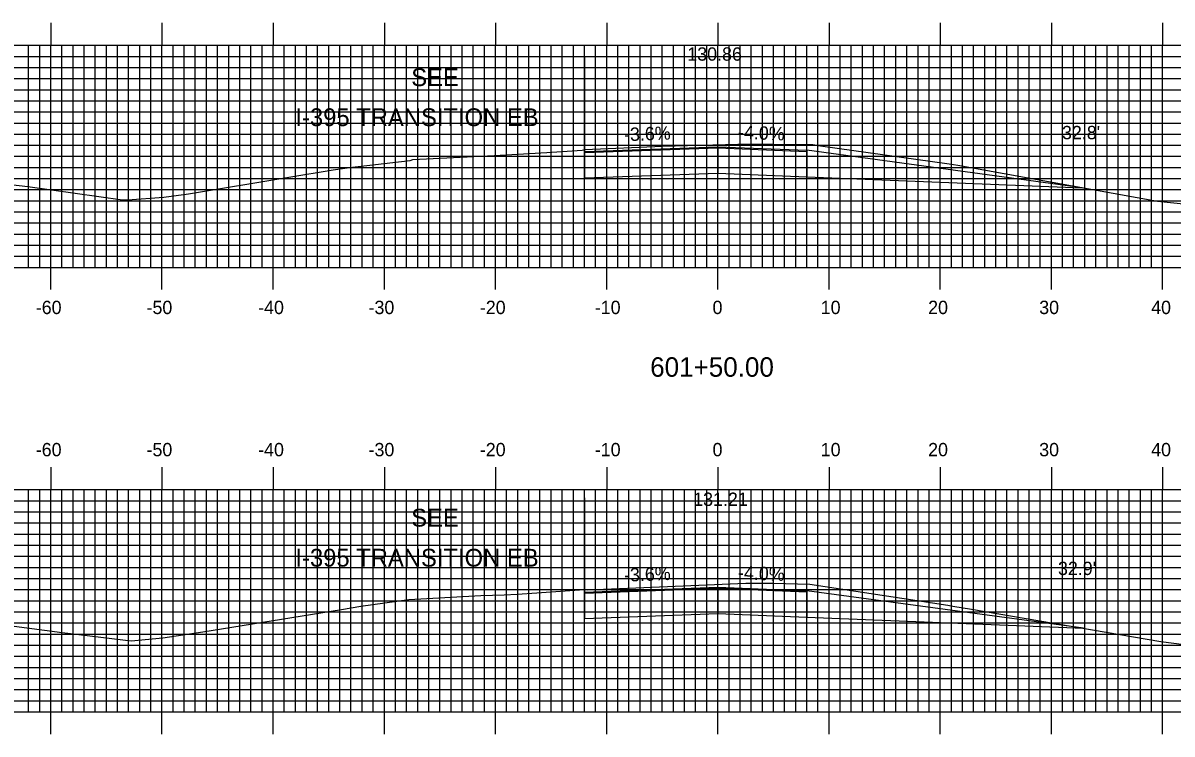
# Model space of a CAD drawing. Extents: x 841388 to 841731, y 363538 to 363758.
# Drawn here: x 841491.4 to 841594.7, y 363633.7 to 363697.7 of the extents above; entities that cross this region are included whole.
import ezdxf

# ---------------------------------------------------------------- set-up
doc = ezdxf.new("R2010")
doc.units = 0
for name, color, linetype in [('ANNOTATION', 7, 'Continuous'), ('D_Roadway_Centerline', 7, 'Continuous'), ('D_Roadway_Centerline_Text', 7, 'Continuous'), ('D_Roadway_Edge_Shoulder', 7, 'Continuous'), ('D_Roadway_Edge_TW', 7, 'Continuous'), ('D_Roadway_SubGrade', 7, 'Continuous'), ('D_Text_Standard', 7, 'Continuous'), ('H_V ANNOTATION', 7, 'Continuous'), ('M_Roadway_Centerline', 7, 'Continuous'), ('MAJOR', 7, 'Continuous'), ('MINOR', 7, 'Continuous'), ('S_Roadway_Centerline', 7, 'Continuous')]:
    doc.layers.add(name, color=color, linetype=linetype)

msp = doc.modelspace()

# ---------------------------------------------------------------- linework, layer by layer
at = {"layer": 'ANNOTATION'}
for p, q in [((841553.86, 363686.45), (841553.86, 363684.2)), ((841541.86, 363686.02), (841541.86, 363683.77)), ((841561.86, 363686.13), (841561.86, 363683.88)), ((841541.86, 363646.38), (841541.86, 363644.13)), ((841553.86, 363646.81), (841553.86, 363644.56)), ((841561.86, 363646.49), (841561.86, 363644.24))]:
    msp.add_line(p, q, dxfattribs=at)
at = {"layer": 'D_Roadway_Centerline'}
for points in [[(841541.86, 363686.15), (841553.86, 363686.58), (841561.86, 363686.26)], [(841541.86, 363646.5), (841553.86, 363646.93), (841561.86, 363646.61)]]:
    msp.add_lwpolyline(points, dxfattribs=at)
at = {"layer": 'D_Roadway_Edge_Shoulder'}
for points in [[(841553.86, 363686.58), (841561.86, 363686.26), (841561.86, 363686.13), (841553.86, 363686.45)], [(841553.86, 363646.93), (841561.86, 363646.61), (841561.86, 363646.49), (841553.86, 363646.81)]]:
    msp.add_lwpolyline(points, close=True, dxfattribs=at)
at = {"layer": 'D_Roadway_Edge_TW'}
for points in [[(841541.86, 363686.15), (841553.86, 363686.58), (841553.86, 363686.45), (841541.86, 363686.02)], [(841541.86, 363646.5), (841553.86, 363646.93), (841553.86, 363646.81), (841541.86, 363646.38)]]:
    msp.add_lwpolyline(points, close=True, dxfattribs=at)
for points in [[(841541.86, 363686.15), (841541.86, 363686.02)], [(841541.86, 363646.5), (841541.86, 363646.38)]]:
    msp.add_lwpolyline(points, dxfattribs=at)
at = {"layer": 'D_Roadway_SubGrade'}
for p, q in [((841541.86, 363694.62), (841541.86, 363686.02)), ((841553.86, 363686.45), (841553.86, 363684.2)), ((841561.86, 363686.13), (841561.86, 363683.88)), ((841541.86, 363654.97), (841541.86, 363646.38)), ((841553.86, 363646.81), (841553.86, 363644.56)), ((841561.86, 363646.49), (841561.86, 363644.24))]:
    msp.add_line(p, q, dxfattribs=at)
for points in [[(841561.86, 363683.88), (841586.63, 363682.89), (841561.86, 363686.26)], [(841541.86, 363686.02), (841541.86, 363683.77), (841553.86, 363684.2), (841561.86, 363683.88)], [(841541.86, 363646.38), (841541.86, 363644.13), (841553.86, 363644.56), (841561.86, 363644.24)], [(841561.86, 363644.24), (841586.75, 363643.24), (841561.86, 363646.61)]]:
    msp.add_lwpolyline(points, dxfattribs=at)
at = {"layer": 'MAJOR'}
for p, q in [((841493.86, 363697.73), (841493.86, 363695.72)), ((841503.86, 363697.73), (841503.86, 363695.72)), ((841513.86, 363697.73), (841513.86, 363695.72)), ((841523.86, 363697.73), (841523.86, 363695.72)), ((841533.86, 363697.73), (841533.86, 363695.72)), ((841543.86, 363697.73), (841543.86, 363695.72)), ((841553.86, 363697.73), (841553.86, 363695.72)), ((841563.86, 363697.73), (841563.86, 363695.72)), ((841573.86, 363697.73), (841573.86, 363695.72)), ((841583.86, 363697.73), (841583.86, 363695.72)), ((841593.86, 363697.73), (841593.86, 363695.72)), ((841413.86, 363695.72), (841693.86, 363695.72)), ((841413.86, 363695.72), (841693.86, 363695.72)), ((841493.86, 363675.72), (841493.86, 363695.72)), ((841503.86, 363675.72), (841503.86, 363695.72)), ((841513.86, 363675.72), (841513.86, 363695.72)), ((841523.86, 363675.72), (841523.86, 363695.72)), ((841533.86, 363675.72), (841533.86, 363695.72)), ((841543.86, 363675.72), (841543.86, 363695.72)), ((841553.86, 363675.72), (841553.86, 363695.72)), ((841563.86, 363675.72), (841563.86, 363695.72)), ((841573.86, 363675.72), (841573.86, 363695.72)), ((841583.86, 363675.72), (841583.86, 363695.72)), ((841593.86, 363675.72), (841593.86, 363695.72)), ((841413.86, 363690.72), (841693.86, 363690.72)), ((841413.86, 363685.72), (841693.86, 363685.72)), ((841413.86, 363680.72), (841693.86, 363680.72)), ((841413.86, 363675.72), (841693.86, 363675.72)), ((841413.86, 363675.72), (841693.86, 363675.72)), ((841493.86, 363673.72), (841493.86, 363675.72)), ((841503.86, 363673.72), (841503.86, 363675.72)), ((841513.86, 363673.72), (841513.86, 363675.72)), ((841523.86, 363673.72), (841523.86, 363675.72)), ((841533.86, 363673.72), (841533.86, 363675.72)), ((841543.86, 363673.72), (841543.86, 363675.72)), ((841553.86, 363673.72), (841553.86, 363675.72)), ((841563.86, 363673.72), (841563.86, 363675.72)), ((841573.86, 363673.72), (841573.86, 363675.72)), ((841583.86, 363673.72), (841583.86, 363675.72)), ((841593.86, 363673.72), (841593.86, 363675.72)), ((841493.86, 363657.73), (841493.86, 363655.72)), ((841503.86, 363657.73), (841503.86, 363655.72)), ((841513.86, 363657.73), (841513.86, 363655.72)), ((841523.86, 363657.73), (841523.86, 363655.72)), ((841533.86, 363657.73), (841533.86, 363655.72)), ((841543.86, 363657.73), (841543.86, 363655.72)), ((841553.86, 363657.73), (841553.86, 363655.72)), ((841563.86, 363657.73), (841563.86, 363655.72)), ((841573.86, 363657.73), (841573.86, 363655.72)), ((841583.86, 363657.73), (841583.86, 363655.72)), ((841593.86, 363657.73), (841593.86, 363655.72)), ((841413.86, 363655.72), (841693.86, 363655.72)), ((841413.86, 363655.72), (841693.86, 363655.72)), ((841493.86, 363635.72), (841493.86, 363655.72)), ((841503.86, 363635.72), (841503.86, 363655.72)), ((841513.86, 363635.72), (841513.86, 363655.72)), ((841523.86, 363635.72), (841523.86, 363655.72)), ((841533.86, 363635.72), (841533.86, 363655.72)), ((841543.86, 363635.72), (841543.86, 363655.72)), ((841553.86, 363635.72), (841553.86, 363655.72)), ((841563.86, 363635.72), (841563.86, 363655.72)), ((841573.86, 363635.72), (841573.86, 363655.72)), ((841583.86, 363635.72), (841583.86, 363655.72)), ((841593.86, 363635.72), (841593.86, 363655.72)), ((841413.86, 363650.72), (841693.86, 363650.72)), ((841413.86, 363645.72), (841693.86, 363645.72)), ((841413.86, 363640.72), (841693.86, 363640.72)), ((841413.86, 363635.72), (841693.86, 363635.72)), ((841413.86, 363635.72), (841693.86, 363635.72)), ((841493.86, 363633.72), (841493.86, 363635.72)), ((841503.86, 363633.72), (841503.86, 363635.72)), ((841513.86, 363633.72), (841513.86, 363635.72)), ((841523.86, 363633.72), (841523.86, 363635.72)), ((841533.86, 363633.72), (841533.86, 363635.72)), ((841543.86, 363633.72), (841543.86, 363635.72)), ((841553.86, 363633.72), (841553.86, 363635.72)), ((841563.86, 363633.72), (841563.86, 363635.72)), ((841573.86, 363633.72), (841573.86, 363635.72)), ((841583.86, 363633.72), (841583.86, 363635.72)), ((841593.86, 363633.72), (841593.86, 363635.72))]:
    msp.add_line(p, q, dxfattribs=at)
at = {"layer": 'MINOR'}
for p, q in [((841491.86, 363675.72), (841491.86, 363695.72)), ((841492.86, 363675.72), (841492.86, 363695.72)), ((841494.86, 363675.72), (841494.86, 363695.72)), ((841495.86, 363675.72), (841495.86, 363695.72)), ((841496.86, 363675.72), (841496.86, 363695.72)), ((841497.86, 363675.72), (841497.86, 363695.72)), ((841498.86, 363675.72), (841498.86, 363695.72)), ((841499.86, 363675.72), (841499.86, 363695.72)), ((841500.86, 363675.72), (841500.86, 363695.72)), ((841501.86, 363675.72), (841501.86, 363695.72)), ((841502.86, 363675.72), (841502.86, 363695.72)), ((841504.86, 363675.72), (841504.86, 363695.72)), ((841505.86, 363675.72), (841505.86, 363695.72)), ((841506.86, 363675.72), (841506.86, 363695.72)), ((841507.86, 363675.72), (841507.86, 363695.72)), ((841508.86, 363675.72), (841508.86, 363695.72)), ((841509.86, 363675.72), (841509.86, 363695.72)), ((841510.86, 363675.72), (841510.86, 363695.72)), ((841511.86, 363675.72), (841511.86, 363695.72)), ((841512.86, 363675.72), (841512.86, 363695.72)), ((841514.86, 363675.72), (841514.86, 363695.72)), ((841515.86, 363675.72), (841515.86, 363695.72)), ((841516.86, 363675.72), (841516.86, 363695.72)), ((841517.86, 363675.72), (841517.86, 363695.72)), ((841518.86, 363675.72), (841518.86, 363695.72)), ((841519.86, 363675.72), (841519.86, 363695.72)), ((841520.86, 363675.72), (841520.86, 363695.72)), ((841521.86, 363675.72), (841521.86, 363695.72)), ((841522.86, 363675.72), (841522.86, 363695.72)), ((841524.86, 363675.72), (841524.86, 363695.72)), ((841525.86, 363675.72), (841525.86, 363695.72)), ((841526.86, 363675.72), (841526.86, 363695.72)), ((841527.86, 363675.72), (841527.86, 363695.72)), ((841528.86, 363675.72), (841528.86, 363695.72)), ((841529.86, 363675.72), (841529.86, 363695.72)), ((841530.86, 363675.72), (841530.86, 363695.72)), ((841531.86, 363675.72), (841531.86, 363695.72)), ((841532.86, 363675.72), (841532.86, 363695.72)), ((841534.86, 363675.72), (841534.86, 363695.72)), ((841535.86, 363675.72), (841535.86, 363695.72)), ((841536.86, 363675.72), (841536.86, 363695.72)), ((841537.86, 363675.72), (841537.86, 363695.72)), ((841538.86, 363675.72), (841538.86, 363695.72)), ((841539.86, 363675.72), (841539.86, 363695.72)), ((841540.86, 363675.72), (841540.86, 363695.72)), ((841541.86, 363675.72), (841541.86, 363695.72)), ((841542.86, 363675.72), (841542.86, 363695.72)), ((841544.86, 363675.72), (841544.86, 363695.72)), ((841545.86, 363675.72), (841545.86, 363695.72)), ((841546.86, 363675.72), (841546.86, 363695.72)), ((841547.86, 363675.72), (841547.86, 363695.72)), ((841548.86, 363675.72), (841548.86, 363695.72)), ((841549.86, 363675.72), (841549.86, 363695.72)), ((841550.86, 363675.72), (841550.86, 363695.72)), ((841551.86, 363675.72), (841551.86, 363695.72)), ((841552.86, 363675.72), (841552.86, 363695.72)), ((841554.86, 363675.72), (841554.86, 363695.72)), ((841555.86, 363675.72), (841555.86, 363695.72)), ((841556.86, 363675.72), (841556.86, 363695.72)), ((841557.86, 363675.72), (841557.86, 363695.72)), ((841558.86, 363675.72), (841558.86, 363695.72)), ((841559.86, 363675.72), (841559.86, 363695.72)), ((841560.86, 363675.72), (841560.86, 363695.72)), ((841561.86, 363675.72), (841561.86, 363695.72)), ((841562.86, 363675.72), (841562.86, 363695.72)), ((841564.86, 363675.72), (841564.86, 363695.72)), ((841565.86, 363675.72), (841565.86, 363695.72)), ((841566.86, 363675.72), (841566.86, 363695.72)), ((841567.86, 363675.72), (841567.86, 363695.72)), ((841568.86, 363675.72), (841568.86, 363695.72)), ((841569.86, 363675.72), (841569.86, 363695.72)), ((841570.86, 363675.72), (841570.86, 363695.72)), ((841571.86, 363675.72), (841571.86, 363695.72)), ((841572.86, 363675.72), (841572.86, 363695.72)), ((841574.86, 363675.72), (841574.86, 363695.72)), ((841575.86, 363675.72), (841575.86, 363695.72)), ((841576.86, 363675.72), (841576.86, 363695.72)), ((841577.86, 363675.72), (841577.86, 363695.72)), ((841578.86, 363675.72), (841578.86, 363695.72)), ((841579.86, 363675.72), (841579.86, 363695.72)), ((841580.86, 363675.72), (841580.86, 363695.72)), ((841581.86, 363675.72), (841581.86, 363695.72)), ((841582.86, 363675.72), (841582.86, 363695.72)), ((841584.86, 363675.72), (841584.86, 363695.72)), ((841585.86, 363675.72), (841585.86, 363695.72)), ((841586.86, 363675.72), (841586.86, 363695.72)), ((841587.86, 363675.72), (841587.86, 363695.72)), ((841588.86, 363675.72), (841588.86, 363695.72)), ((841589.86, 363675.72), (841589.86, 363695.72)), ((841590.86, 363675.72), (841590.86, 363695.72)), ((841591.86, 363675.72), (841591.86, 363695.72)), ((841592.86, 363675.72), (841592.86, 363695.72)), ((841413.86, 363694.72), (841693.86, 363694.72)), ((841413.86, 363693.72), (841693.86, 363693.72)), ((841413.86, 363692.72), (841693.86, 363692.72)), ((841413.86, 363691.72), (841693.86, 363691.72)), ((841413.86, 363689.72), (841693.86, 363689.72)), ((841413.86, 363688.72), (841693.86, 363688.72)), ((841413.86, 363687.72), (841693.86, 363687.72)), ((841413.86, 363686.72), (841693.86, 363686.72)), ((841413.86, 363684.72), (841693.86, 363684.72)), ((841413.86, 363683.72), (841693.86, 363683.72)), ((841413.86, 363682.72), (841693.86, 363682.72)), ((841413.86, 363681.72), (841693.86, 363681.72)), ((841413.86, 363679.72), (841693.86, 363679.72)), ((841413.86, 363678.72), (841693.86, 363678.72)), ((841413.86, 363677.72), (841693.86, 363677.72)), ((841413.86, 363676.72), (841693.86, 363676.72)), ((841491.86, 363635.72), (841491.86, 363655.72)), ((841492.86, 363635.72), (841492.86, 363655.72)), ((841494.86, 363635.72), (841494.86, 363655.72)), ((841495.86, 363635.72), (841495.86, 363655.72)), ((841496.86, 363635.72), (841496.86, 363655.72)), ((841497.86, 363635.72), (841497.86, 363655.72)), ((841498.86, 363635.72), (841498.86, 363655.72)), ((841499.86, 363635.72), (841499.86, 363655.72)), ((841500.86, 363635.72), (841500.86, 363655.72)), ((841501.86, 363635.72), (841501.86, 363655.72)), ((841502.86, 363635.72), (841502.86, 363655.72)), ((841504.86, 363635.72), (841504.86, 363655.72)), ((841505.86, 363635.72), (841505.86, 363655.72)), ((841506.86, 363635.72), (841506.86, 363655.72)), ((841507.86, 363635.72), (841507.86, 363655.72)), ((841508.86, 363635.72), (841508.86, 363655.72)), ((841509.86, 363635.72), (841509.86, 363655.72)), ((841510.86, 363635.72), (841510.86, 363655.72)), ((841511.86, 363635.72), (841511.86, 363655.72)), ((841512.86, 363635.72), (841512.86, 363655.72)), ((841514.86, 363635.72), (841514.86, 363655.72)), ((841515.86, 363635.72), (841515.86, 363655.72)), ((841516.86, 363635.72), (841516.86, 363655.72)), ((841517.86, 363635.72), (841517.86, 363655.72)), ((841518.86, 363635.72), (841518.86, 363655.72)), ((841519.86, 363635.72), (841519.86, 363655.72)), ((841520.86, 363635.72), (841520.86, 363655.72)), ((841521.86, 363635.72), (841521.86, 363655.72)), ((841522.86, 363635.72), (841522.86, 363655.72)), ((841524.86, 363635.72), (841524.86, 363655.72)), ((841525.86, 363635.72), (841525.86, 363655.72)), ((841526.86, 363635.72), (841526.86, 363655.72)), ((841527.86, 363635.72), (841527.86, 363655.72)), ((841528.86, 363635.72), (841528.86, 363655.72)), ((841529.86, 363635.72), (841529.86, 363655.72)), ((841530.86, 363635.72), (841530.86, 363655.72)), ((841531.86, 363635.72), (841531.86, 363655.72)), ((841532.86, 363635.72), (841532.86, 363655.72)), ((841534.86, 363635.72), (841534.86, 363655.72)), ((841535.86, 363635.72), (841535.86, 363655.72)), ((841536.86, 363635.72), (841536.86, 363655.72)), ((841537.86, 363635.72), (841537.86, 363655.72)), ((841538.86, 363635.72), (841538.86, 363655.72)), ((841539.86, 363635.72), (841539.86, 363655.72)), ((841540.86, 363635.72), (841540.86, 363655.72)), ((841541.86, 363635.72), (841541.86, 363655.72)), ((841542.86, 363635.72), (841542.86, 363655.72)), ((841544.86, 363635.72), (841544.86, 363655.72)), ((841545.86, 363635.72), (841545.86, 363655.72)), ((841546.86, 363635.72), (841546.86, 363655.72)), ((841547.86, 363635.72), (841547.86, 363655.72)), ((841548.86, 363635.72), (841548.86, 363655.72)), ((841549.86, 363635.72), (841549.86, 363655.72)), ((841550.86, 363635.72), (841550.86, 363655.72)), ((841551.86, 363635.72), (841551.86, 363655.72)), ((841552.86, 363635.72), (841552.86, 363655.72)), ((841554.86, 363635.72), (841554.86, 363655.72)), ((841555.86, 363635.72), (841555.86, 363655.72)), ((841556.86, 363635.72), (841556.86, 363655.72)), ((841557.86, 363635.72), (841557.86, 363655.72)), ((841558.86, 363635.72), (841558.86, 363655.72)), ((841559.86, 363635.72), (841559.86, 363655.72)), ((841560.86, 363635.72), (841560.86, 363655.72)), ((841561.86, 363635.72), (841561.86, 363655.72)), ((841562.86, 363635.72), (841562.86, 363655.72)), ((841564.86, 363635.72), (841564.86, 363655.72)), ((841565.86, 363635.72), (841565.86, 363655.72)), ((841566.86, 363635.72), (841566.86, 363655.72)), ((841567.86, 363635.72), (841567.86, 363655.72)), ((841568.86, 363635.72), (841568.86, 363655.72)), ((841569.86, 363635.72), (841569.86, 363655.72)), ((841570.86, 363635.72), (841570.86, 363655.72)), ((841571.86, 363635.72), (841571.86, 363655.72)), ((841572.86, 363635.72), (841572.86, 363655.72)), ((841574.86, 363635.72), (841574.86, 363655.72)), ((841575.86, 363635.72), (841575.86, 363655.72)), ((841576.86, 363635.72), (841576.86, 363655.72)), ((841577.86, 363635.72), (841577.86, 363655.72)), ((841578.86, 363635.72), (841578.86, 363655.72)), ((841579.86, 363635.72), (841579.86, 363655.72)), ((841580.86, 363635.72), (841580.86, 363655.72)), ((841581.86, 363635.72), (841581.86, 363655.72)), ((841582.86, 363635.72), (841582.86, 363655.72)), ((841584.86, 363635.72), (841584.86, 363655.72)), ((841585.86, 363635.72), (841585.86, 363655.72)), ((841586.86, 363635.72), (841586.86, 363655.72)), ((841587.86, 363635.72), (841587.86, 363655.72)), ((841588.86, 363635.72), (841588.86, 363655.72)), ((841589.86, 363635.72), (841589.86, 363655.72)), ((841590.86, 363635.72), (841590.86, 363655.72)), ((841591.86, 363635.72), (841591.86, 363655.72)), ((841592.86, 363635.72), (841592.86, 363655.72)), ((841413.86, 363654.72), (841693.86, 363654.72)), ((841413.86, 363653.72), (841693.86, 363653.72)), ((841413.86, 363652.72), (841693.86, 363652.72)), ((841413.86, 363651.72), (841693.86, 363651.72)), ((841413.86, 363649.72), (841693.86, 363649.72)), ((841413.86, 363648.72), (841693.86, 363648.72)), ((841413.86, 363647.72), (841693.86, 363647.72)), ((841413.86, 363646.72), (841693.86, 363646.72)), ((841413.86, 363644.72), (841693.86, 363644.72)), ((841413.86, 363643.72), (841693.86, 363643.72)), ((841413.86, 363642.72), (841693.86, 363642.72)), ((841413.86, 363641.72), (841693.86, 363641.72)), ((841413.86, 363639.72), (841693.86, 363639.72)), ((841413.86, 363638.72), (841693.86, 363638.72)), ((841413.86, 363637.72), (841693.86, 363637.72)), ((841413.86, 363636.72), (841693.86, 363636.72))]:
    msp.add_line(p, q, dxfattribs=at)
at = {"layer": 'S_Roadway_Centerline'}
for points in [[(841487.08, 363683.53), (841491.81, 363682.99), (841500.32, 363681.8), (841500.75, 363681.79), (841504.04, 363682.03), (841506.26, 363682.33), (841515.26, 363683.84), (841519.27, 363684.5), (841520.74, 363684.7), (841526.19, 363685.35), (841526.43, 363685.44), (841533.74, 363685.8), (841538.47, 363686.05), (841541.65, 363686.26), (841541.89, 363686.34), (841548.88, 363686.63), (841556.78, 363686.85), (841560.82, 363686.79), (841562.31, 363686.78), (841562.39, 363686.77), (841563.1, 363686.67), (841574.66, 363685.05), (841575.45, 363684.93), (841577.79, 363684.49), (841593.41, 363681.67), (841597.22, 363681.28)], [(841487.35, 363643.84), (841494.89, 363642.85), (841501.1, 363642.12), (841503.93, 363642.37), (841507.53, 363642.93), (841520.02, 363644.93), (841521.76, 363645.22), (841526.05, 363645.83), (841531.47, 363646.12), (841532.54, 363646.18), (841534.65, 363646.25), (841535.8, 363646.32), (841537.58, 363646.43), (841541.82, 363646.72), (841542.09, 363646.7), (841547.21, 363646.92), (841556.37, 363647.29), (841558.84, 363647.31), (841562.14, 363647.21), (841574.55, 363645.31), (841574.98, 363645.24), (841576.66, 363644.97), (841593.7, 363642.05), (841596.73, 363641.67)]]:
    msp.add_lwpolyline(points, dxfattribs=at)

# ---------------------------------------------------------------- texts
at = {"layer": 'ANNOTATION'}
for s, p in [('SEE', (841526.28, 363692.04)), ('I-395 TRANSITION EB', (841515.86, 363688.44)), ('SEE', (841526.28, 363652.39)), ('I-395 TRANSITION EB', (841515.86, 363648.79))]:
    msp.add_text(s, height=1.6, dxfattribs=at).set_placement(p)
for s, rotation, p in [('-3.6%', 2.0618, (841545.44, 363687.08)), ('-4.0%', 357.7094, (841555.65, 363687.31)), ('-3.6%', 2.0618, (841545.44, 363647.43)), ('-4.0%', 357.7094, (841555.65, 363647.66))]:
    msp.add_text(s, height=1.2, rotation=rotation, dxfattribs=at).set_placement(p)
at = {"layer": 'D_Roadway_Centerline_Text'}
for s, p in [('130.86', (841551.11, 363694.33)), ('131.21', (841551.64, 363654.25))]:
    msp.add_text(s, height=1.2, dxfattribs=at).set_placement(p)
at = {"layer": 'D_Text_Standard'}
for s, p in [("32.8'", (841584.81, 363687.26)), ("32.9'", (841584.45, 363648.03))]:
    msp.add_text(s, height=1.2, dxfattribs=at).set_placement(p)
at = {"layer": 'H_V ANNOTATION'}
for s, height, p in [('-60', 1.2, (841492.51, 363671.52)), ('-50', 1.2, (841502.47, 363671.52)), ('-40', 1.2, (841512.51, 363671.52)), ('-30', 1.2, (841522.44, 363671.52)), ('-20', 1.2, (841532.45, 363671.52)), ('-10', 1.2, (841542.79, 363671.52)), ('0', 1.2, (841553.38, 363671.52)), ('10', 1.2, (841563.11, 363671.52)), ('20', 1.2, (841572.77, 363671.52)), ('30', 1.2, (841582.76, 363671.52)), ('40', 1.2, (841592.83, 363671.52)), ('601+50.00', 1.75, (841547.77, 363665.88)), ('-60', 1.2, (841492.51, 363658.72)), ('-50', 1.2, (841502.47, 363658.72)), ('-40', 1.2, (841512.51, 363658.72)), ('-30', 1.2, (841522.44, 363658.72)), ('-20', 1.2, (841532.45, 363658.72)), ('-10', 1.2, (841542.79, 363658.72)), ('0', 1.2, (841553.38, 363658.72)), ('10', 1.2, (841563.11, 363658.72)), ('20', 1.2, (841572.77, 363658.72)), ('30', 1.2, (841582.76, 363658.72)), ('40', 1.2, (841592.83, 363658.72))]:
    msp.add_text(s, height=height, dxfattribs=at).set_placement(p)
at = {"layer": 'M_Roadway_Centerline'}
for s, p in [('C', (841541.88, 363686.34)), ('L', (841541.89, 363686.33)), ('C', (841541.82, 363646.72)), ('L', (841541.82, 363646.71))]:
    msp.add_text(s, height=0.0146, dxfattribs=at).set_placement(p)

doc.saveas('drawing.dxf')
